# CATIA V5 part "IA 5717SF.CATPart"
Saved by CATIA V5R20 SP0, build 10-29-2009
Part number: IA 5717SF
Revision: ANY
Definition: UNKNOWN
Nomenclature: IA 5717SF
Source: Unknown
Bounding box of the stored display mesh (mm): x -2.85 to 2.85, y -7.925 to 9.045, z -2.711 to 2.711
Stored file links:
  C:\Users\Utente\Desktop\IO LAVORO\3D X SITO CF\CUMSA\3D files IA\IA 5717SF\IA 5717SF.CATPart
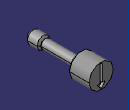
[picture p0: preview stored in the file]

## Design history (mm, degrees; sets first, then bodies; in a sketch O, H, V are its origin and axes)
Body1 "Cortar-Extruir2" (main body)
  Solid1: solid without history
